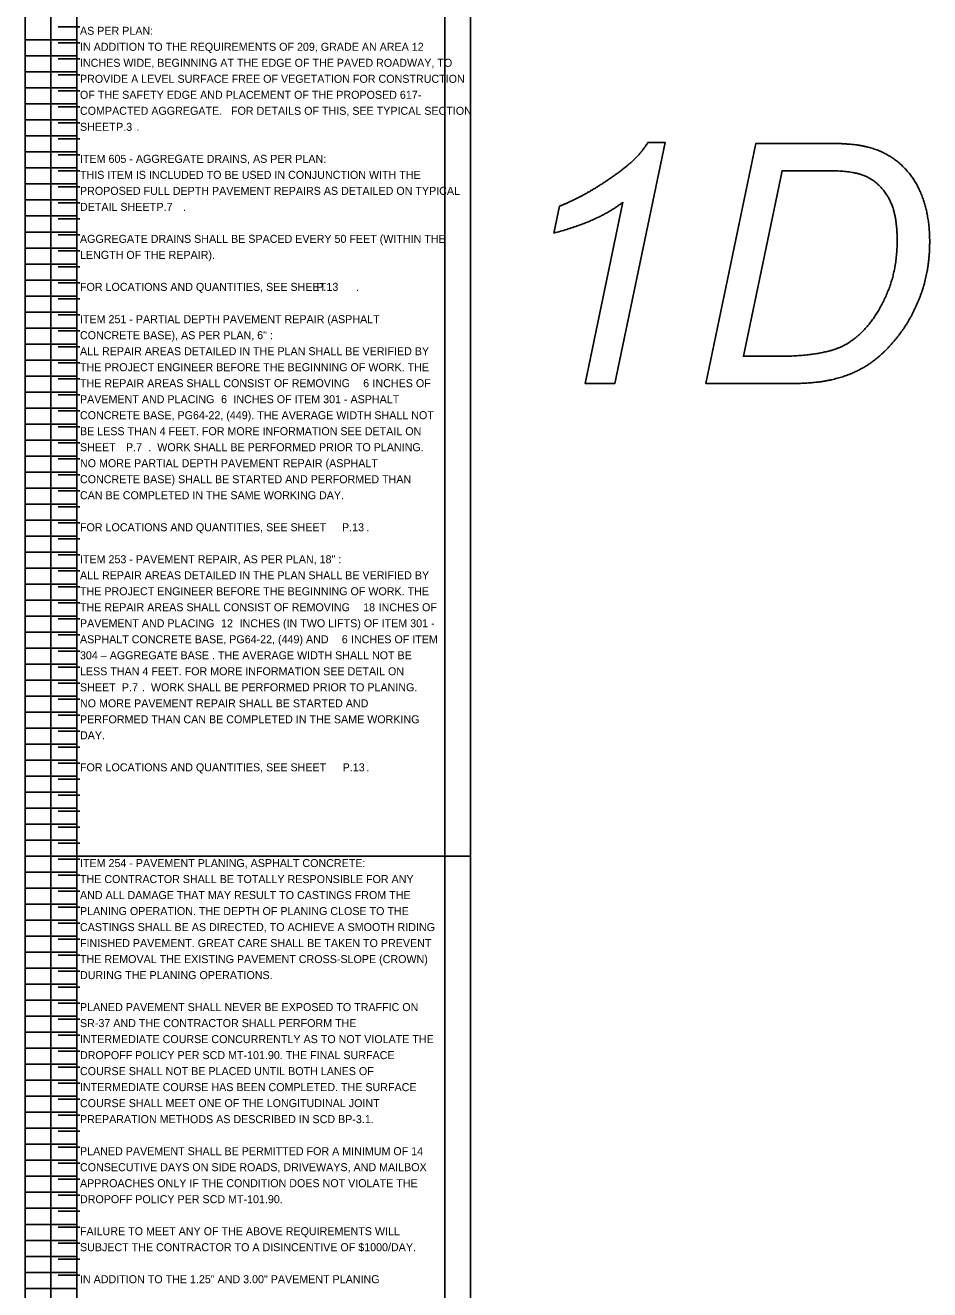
# Model space of a CAD drawing. Extents: x 12316 to 12541, y 1124 to 1850.
# Drawn here: x 12521.92 to 12537.74, y 1761.57 to 1783.69 of the extents above; entities that cross this region are included whole.
import ezdxf

# ---------------------------------------------------------------- set-up
doc = ezdxf.new("R2010")
doc.units = 0
for name, color, linetype in [('SC_Scratch1', 7, 'Continuous'), ('SH_Data', 7, 'Continuous'), ('SH_Text', 7, 'Continuous')]:
    doc.layers.add(name, color=color, linetype=linetype)

msp = doc.modelspace()

# ---------------------------------------------------------------- linework, layer by layer
at = {"layer": 'SC_Scratch1'}
for p, q in [((12521.919, 1769.151), (12521.919, 1789.311)), ((12522.819, 1769.151), (12522.819, 1789.311)), ((12522.819, 1789.311), (12522.819, 1769.151)), ((12522.876, 1783.661), (12522.492, 1783.661)), ((12521.919, 1783.431), (12522.819, 1783.431)), ((12522.876, 1783.381), (12522.492, 1783.381)), ((12521.919, 1783.151), (12522.819, 1783.151)), ((12522.876, 1783.101), (12522.492, 1783.101)), ((12521.919, 1782.871), (12522.819, 1782.871)), ((12522.876, 1782.821), (12522.492, 1782.821)), ((12521.919, 1782.591), (12522.819, 1782.591)), ((12522.876, 1782.541), (12522.492, 1782.541)), ((12521.919, 1782.311), (12522.819, 1782.311)), ((12522.876, 1782.261), (12522.492, 1782.261)), ((12521.919, 1782.031), (12522.819, 1782.031)), ((12522.876, 1781.981), (12522.492, 1781.981)), ((12521.919, 1781.751), (12522.819, 1781.751)), ((12522.876, 1781.701), (12522.492, 1781.701)), ((12521.919, 1781.471), (12522.819, 1781.471)), ((12522.876, 1781.421), (12522.492, 1781.421)), ((12521.919, 1781.191), (12522.819, 1781.191)), ((12522.876, 1781.141), (12522.492, 1781.141)), ((12521.919, 1780.911), (12522.819, 1780.911)), ((12522.876, 1780.861), (12522.492, 1780.861)), ((12521.919, 1780.631), (12522.819, 1780.631)), ((12522.876, 1780.581), (12522.492, 1780.581)), ((12531.166, 1780.052), (12531.263, 1780.523)), ((12521.919, 1780.351), (12522.819, 1780.351)), ((12522.876, 1780.301), (12522.492, 1780.301)), ((12521.919, 1780.071), (12522.819, 1780.071)), ((12522.876, 1780.021), (12522.492, 1780.021)), ((12521.919, 1779.791), (12522.819, 1779.791)), ((12522.876, 1779.741), (12522.492, 1779.741)), ((12521.919, 1779.511), (12522.819, 1779.511)), ((12522.876, 1779.461), (12522.492, 1779.461)), ((12521.919, 1779.231), (12522.819, 1779.231)), ((12522.876, 1779.181), (12522.492, 1779.181)), ((12521.919, 1778.951), (12522.819, 1778.951)), ((12522.876, 1778.901), (12522.492, 1778.901)), ((12521.919, 1778.671), (12522.819, 1778.671)), ((12522.876, 1778.621), (12522.492, 1778.621)), ((12521.919, 1778.391), (12522.819, 1778.391)), ((12522.876, 1778.341), (12522.492, 1778.341)), ((12521.919, 1778.111), (12522.819, 1778.111)), ((12522.876, 1778.061), (12522.492, 1778.061)), ((12521.919, 1777.831), (12522.819, 1777.831)), ((12522.876, 1777.781), (12522.492, 1777.781)), ((12521.919, 1777.551), (12522.819, 1777.551)), ((12522.876, 1777.501), (12522.492, 1777.501)), ((12521.919, 1777.271), (12522.819, 1777.271)), ((12522.876, 1777.221), (12522.492, 1777.221)), ((12521.919, 1776.991), (12522.819, 1776.991)), ((12522.876, 1776.941), (12522.492, 1776.941)), ((12521.919, 1776.711), (12522.819, 1776.711)), ((12522.876, 1776.661), (12522.492, 1776.661)), ((12521.919, 1776.431), (12522.819, 1776.431)), ((12522.876, 1776.381), (12522.492, 1776.381)), ((12521.919, 1776.151), (12522.819, 1776.151)), ((12522.876, 1776.101), (12522.492, 1776.101)), ((12521.919, 1775.871), (12522.819, 1775.871)), ((12522.876, 1775.821), (12522.492, 1775.821)), ((12521.919, 1775.591), (12522.819, 1775.591)), ((12522.876, 1775.541), (12522.492, 1775.541)), ((12521.919, 1775.311), (12522.819, 1775.311)), ((12522.876, 1775.261), (12522.492, 1775.261)), ((12521.919, 1775.031), (12522.819, 1775.031)), ((12522.876, 1774.981), (12522.492, 1774.981)), ((12521.919, 1774.751), (12522.819, 1774.751)), ((12522.876, 1774.701), (12522.492, 1774.701)), ((12521.919, 1774.471), (12522.819, 1774.471)), ((12522.876, 1774.421), (12522.492, 1774.421)), ((12521.919, 1774.191), (12522.819, 1774.191)), ((12522.876, 1774.141), (12522.492, 1774.141)), ((12521.919, 1773.911), (12522.819, 1773.911)), ((12522.876, 1773.861), (12522.492, 1773.861)), ((12521.919, 1773.631), (12522.819, 1773.631)), ((12522.876, 1773.581), (12522.492, 1773.581)), ((12521.919, 1773.351), (12522.819, 1773.351)), ((12522.876, 1773.301), (12522.492, 1773.301)), ((12521.919, 1773.071), (12522.819, 1773.071)), ((12522.876, 1773.021), (12522.492, 1773.021)), ((12521.919, 1772.791), (12522.819, 1772.791)), ((12522.876, 1772.741), (12522.492, 1772.741)), ((12521.919, 1772.511), (12522.819, 1772.511)), ((12522.876, 1772.461), (12522.492, 1772.461)), ((12521.919, 1772.231), (12522.819, 1772.231)), ((12522.876, 1772.181), (12522.492, 1772.181)), ((12521.919, 1771.951), (12522.819, 1771.951)), ((12522.876, 1771.901), (12522.492, 1771.901)), ((12521.919, 1771.671), (12522.819, 1771.671)), ((12522.876, 1771.621), (12522.492, 1771.621)), ((12521.919, 1771.391), (12522.819, 1771.391)), ((12522.876, 1771.341), (12522.492, 1771.341)), ((12521.919, 1771.111), (12522.819, 1771.111)), ((12522.876, 1771.061), (12522.492, 1771.061)), ((12521.919, 1770.831), (12522.819, 1770.831)), ((12522.876, 1770.781), (12522.492, 1770.781)), ((12521.919, 1770.551), (12522.819, 1770.551)), ((12522.876, 1770.501), (12522.492, 1770.501)), ((12521.919, 1770.271), (12522.819, 1770.271)), ((12522.876, 1770.221), (12522.492, 1770.221)), ((12521.919, 1769.991), (12522.819, 1769.991)), ((12522.876, 1769.941), (12522.492, 1769.941)), ((12521.919, 1769.711), (12522.819, 1769.711)), ((12522.876, 1769.661), (12522.492, 1769.661)), ((12521.919, 1769.431), (12522.819, 1769.431)), ((12522.876, 1769.381), (12522.492, 1769.381)), ((12522.819, 1769.381), (12522.819, 1728.831)), ((12521.919, 1769.151), (12522.819, 1769.151)), ((12521.919, 1748.991), (12521.919, 1769.151)), ((12521.919, 1769.151), (12522.819, 1769.151)), ((12522.876, 1769.101), (12522.492, 1769.101)), ((12522.819, 1748.991), (12522.819, 1769.151)), ((12521.919, 1768.871), (12522.819, 1768.871)), ((12522.876, 1768.821), (12522.492, 1768.821)), ((12521.919, 1768.591), (12522.819, 1768.591)), ((12522.876, 1768.541), (12522.492, 1768.541)), ((12521.919, 1768.311), (12522.819, 1768.311)), ((12522.876, 1768.261), (12522.492, 1768.261)), ((12521.919, 1768.031), (12522.819, 1768.031)), ((12522.876, 1767.981), (12522.492, 1767.981)), ((12521.919, 1767.751), (12522.819, 1767.751)), ((12522.876, 1767.701), (12522.492, 1767.701)), ((12521.919, 1767.471), (12522.819, 1767.471)), ((12522.876, 1767.421), (12522.492, 1767.421)), ((12521.919, 1767.191), (12522.819, 1767.191)), ((12522.876, 1767.141), (12522.492, 1767.141)), ((12521.919, 1766.911), (12522.819, 1766.911)), ((12522.876, 1766.861), (12522.492, 1766.861)), ((12521.919, 1766.631), (12522.819, 1766.631)), ((12522.876, 1766.581), (12522.492, 1766.581)), ((12521.919, 1766.351), (12522.819, 1766.351)), ((12522.876, 1766.301), (12522.492, 1766.301)), ((12521.919, 1766.071), (12522.819, 1766.071)), ((12522.876, 1766.021), (12522.492, 1766.021)), ((12521.919, 1765.791), (12522.819, 1765.791)), ((12522.876, 1765.741), (12522.492, 1765.741)), ((12521.919, 1765.511), (12522.819, 1765.511)), ((12522.876, 1765.461), (12522.492, 1765.461)), ((12521.919, 1765.231), (12522.819, 1765.231)), ((12522.876, 1765.181), (12522.492, 1765.181)), ((12521.919, 1764.951), (12522.819, 1764.951)), ((12522.876, 1764.901), (12522.492, 1764.901)), ((12521.919, 1764.671), (12522.819, 1764.671)), ((12522.876, 1764.621), (12522.492, 1764.621)), ((12521.919, 1764.391), (12522.819, 1764.391)), ((12522.876, 1764.341), (12522.492, 1764.341)), ((12521.919, 1764.111), (12522.819, 1764.111)), ((12522.876, 1764.061), (12522.492, 1764.061)), ((12521.919, 1763.831), (12522.819, 1763.831)), ((12522.876, 1763.781), (12522.492, 1763.781)), ((12521.919, 1763.551), (12522.819, 1763.551)), ((12522.876, 1763.501), (12522.492, 1763.501)), ((12521.919, 1763.271), (12522.819, 1763.271)), ((12522.876, 1763.221), (12522.492, 1763.221)), ((12521.919, 1762.991), (12522.819, 1762.991)), ((12522.876, 1762.941), (12522.492, 1762.941)), ((12521.919, 1762.711), (12522.819, 1762.711)), ((12522.876, 1762.661), (12522.492, 1762.661)), ((12521.919, 1762.431), (12522.819, 1762.431)), ((12522.876, 1762.381), (12522.492, 1762.381)), ((12521.919, 1762.151), (12522.819, 1762.151)), ((12522.876, 1762.101), (12522.492, 1762.101)), ((12521.919, 1761.871), (12522.819, 1761.871)), ((12522.876, 1761.821), (12522.492, 1761.821)), ((12521.919, 1761.591), (12522.819, 1761.591))]:
    msp.add_line(p, q, dxfattribs=at)
for points in [[(12522.369, 1789.311), (12529.709, 1789.311), (12529.709, 1769.151), (12522.369, 1769.151)], [(12522.819, 1789.311), (12529.259, 1789.311), (12529.259, 1769.151), (12522.819, 1769.151)], [(12522.369, 1769.151), (12529.709, 1769.151), (12529.709, 1748.991), (12522.369, 1748.991)], [(12522.819, 1769.151), (12529.259, 1769.151), (12529.259, 1748.991), (12522.819, 1748.991)]]:
    msp.add_lwpolyline(points, close=True, dxfattribs=at)
for points in [[(12532.811, 1781.637), (12533.111, 1781.637), (12532.234, 1777.421), (12531.712, 1777.421), (12532.375, 1780.594)], [(12535.966, 1781.621), (12534.699, 1781.621), (12533.822, 1777.421), (12535.335, 1777.421)], [(12535.147, 1777.898), (12534.481, 1777.898), (12535.159, 1781.144), (12535.903, 1781.144)]]:
    msp.add_lwpolyline(points, dxfattribs=at)
for points in [[(12532.593, 1781.36), (12532.707, 1781.474), (12532.811, 1781.637)], [(12536.663, 1781.555), (12536.422, 1781.621), (12535.966, 1781.621)], [(12537.25, 1781.238), (12537.007, 1781.466), (12536.663, 1781.555)], [(12532.027, 1780.926), (12532.404, 1781.174), (12532.593, 1781.36)], [(12535.903, 1781.144), (12536.334, 1781.144), (12536.538, 1781.078)], [(12537.617, 1780.67), (12537.494, 1781.011), (12537.25, 1781.238)], [(12531.263, 1780.523), (12531.65, 1780.677), (12532.027, 1780.926)], [(12536.538, 1781.078), (12536.814, 1780.989), (12536.992, 1780.716)], [(12536.992, 1780.716), (12537.171, 1780.442), (12537.171, 1779.932)], [(12537.74, 1779.905), (12537.74, 1780.329), (12537.617, 1780.67)], [(12532.375, 1780.594), (12531.945, 1780.256), (12531.166, 1780.052)], [(12537.171, 1779.932), (12537.171, 1779.474), (12537.04, 1779.114)], [(12537.587, 1778.981), (12537.74, 1779.398), (12537.74, 1779.905)], [(12537.04, 1779.114), (12536.909, 1778.755), (12536.691, 1778.474)], [(12537.186, 1778.247), (12537.434, 1778.564), (12537.587, 1778.981)], [(12536.691, 1778.474), (12536.525, 1778.262), (12536.321, 1778.133)], [(12536.667, 1777.752), (12536.938, 1777.931), (12537.186, 1778.247)], [(12536.321, 1778.133), (12536.166, 1778.033), (12535.948, 1777.981)], [(12535.948, 1777.981), (12535.597, 1777.898), (12535.147, 1777.898)], [(12536.026, 1777.487), (12536.396, 1777.573), (12536.667, 1777.752)], [(12535.335, 1777.421), (12535.745, 1777.421), (12536.026, 1777.487)]]:
    msp.add_open_spline(points, degree=2, dxfattribs=at)

# ---------------------------------------------------------------- texts
at = {"layer": 'SH_Data'}
for s, p in [('AS PER PLAN:', (12522.876, 1783.521)), ('IN ADDITION TO THE REQUIREMENTS OF 209, GRADE AN AREA 12  ', (12522.876, 1783.241)), ('INCHES WIDE, BEGINNING AT THE EDGE OF THE PAVED ROADWAY, TO ', (12522.876, 1782.961)), ('PROVIDE A LEVEL SURFACE FREE OF VEGETATION FOR CONSTRUCTION ', (12522.876, 1782.681)), ('OF THE SAFETY EDGE AND PLACEMENT OF THE PROPOSED 617-', (12522.876, 1782.401)), ('COMPACTED AGGREGATE.   FOR DETAILS OF THIS, SEE TYPICAL SECTION ', (12522.876, 1782.121)), ('SHEET       .', (12522.876, 1781.841)), ('ITEM 605 - AGGREGATE DRAINS, AS PER PLAN:', (12522.876, 1781.281)), ('THIS ITEM IS INCLUDED TO BE USED IN CONJUNCTION WITH THE ', (12522.876, 1781.001)), ('PROPOSED FULL DEPTH PAVEMENT REPAIRS AS DETAILED ON TYPICAL ', (12522.876, 1780.721)), ('DETAIL SHEET         .', (12522.876, 1780.441)), ('AGGREGATE DRAINS SHALL BE SPACED EVERY 50 FEET (WITHIN THE ', (12522.876, 1779.881)), ('LENGTH OF THE REPAIR).', (12522.876, 1779.601)), ('FOR LOCATIONS AND QUANTITIES, SEE SHEET          .', (12522.876, 1779.041))]:
    msp.add_text(s, height=0.14, dxfattribs=at).set_placement(p)
at = {"layer": 'SH_Text'}
for s, p in [('P.3', (12523.508, 1781.841)), ('P.7', (12524.215, 1780.441)), ('P.13', (12527.01, 1779.041)), ('ITEM 251 - PARTIAL DEPTH PAVEMENT REPAIR (ASPHALT ', (12522.876, 1778.476)), ('CONCRETE BASE), AS PER PLAN, 6" :', (12522.876, 1778.196)), ('ALL REPAIR AREAS DETAILED IN THE PLAN SHALL BE VERIFIED BY ', (12522.876, 1777.916)), ('THE PROJECT ENGINEER BEFORE THE BEGINNING OF WORK. THE ', (12522.876, 1777.636)), ('THE REPAIR AREAS SHALL CONSIST OF REMOVING ', (12522.876, 1777.356)), ('6 ', (12527.83, 1777.356)), ('INCHES OF ', (12527.993, 1777.356)), ('PAVEMENT AND PLACING ', (12522.876, 1777.076)), ('6 ', (12525.344, 1777.076)), (' INCHES OF ITEM 301 - ASPHALT ', (12525.507, 1777.076)), ('CONCRETE BASE, PG64-22, (449). THE AVERAGE WIDTH SHALL NOT ', (12522.876, 1776.796)), ('BE LESS THAN 4 FEET. FOR MORE INFORMATION SEE DETAIL ON ', (12522.876, 1776.516)), ('SHEET', (12522.876, 1776.236)), ('P.7', (12523.681, 1776.236)), ('.  WORK SHALL BE PERFORMED PRIOR TO PLANING. ', (12524.072, 1776.236)), ('NO MORE PARTIAL DEPTH PAVEMENT REPAIR (ASPHALT ', (12522.876, 1775.956)), ('CONCRETE BASE) SHALL BE STARTED AND PERFORMED THAN ', (12522.876, 1775.676)), ('CAN BE COMPLETED IN THE SAME WORKING DAY.', (12522.876, 1775.396)), ('FOR LOCATIONS AND QUANTITIES, SEE SHEET  ', (12522.876, 1774.836)), ('P.13', (12527.46, 1774.836)), (' .', (12527.836, 1774.836)), ('ITEM 253 - PAVEMENT REPAIR, AS PER PLAN, 18" :', (12522.876, 1774.276)), ('ALL REPAIR AREAS DETAILED IN THE PLAN SHALL BE VERIFIED BY ', (12522.876, 1773.996)), ('THE PROJECT ENGINEER BEFORE THE BEGINNING OF WORK. THE ', (12522.876, 1773.716)), ('THE REPAIR AREAS SHALL CONSIST OF REMOVING ', (12522.876, 1773.436)), ('18 ', (12527.83, 1773.436)), ('INCHES OF ', (12528.101, 1773.436)), ('PAVEMENT AND PLACING ', (12522.876, 1773.156)), ('12 ', (12525.344, 1773.156)), (' INCHES (IN TWO LIFTS) OF ITEM 301 - ', (12525.616, 1773.156)), ('ASPHALT CONCRETE BASE, PG64-22, (449) AND ', (12522.876, 1772.876)), ('6', (12527.456, 1772.876)), (' INCHES OF ITEM ', (12527.565, 1772.876)), ('304 – AGGREGATE BASE . THE AVERAGE WIDTH SHALL NOT BE ', (12522.876, 1772.596)), ('LESS THAN 4 FEET. FOR MORE INFORMATION SEE DETAIL ON ', (12522.876, 1772.316)), ('SHEET', (12522.876, 1772.036)), ('P.7', (12523.61, 1772.036)), (' .  WORK SHALL BE PERFORMED PRIOR TO PLANING. ', (12523.909, 1772.036)), ('NO MORE PAVEMENT REPAIR SHALL BE STARTED AND ', (12522.876, 1771.756)), ('PERFORMED THAN CAN BE COMPLETED IN THE SAME WORKING ', (12522.876, 1771.476)), ('DAY.', (12522.876, 1771.196)), ('FOR LOCATIONS AND QUANTITIES, SEE SHEET  ', (12522.876, 1770.636)), ('P.13', (12527.471, 1770.636)), (' .', (12527.836, 1770.636)), ('ITEM 254 - PAVEMENT PLANING, ASPHALT CONCRETE:', (12522.876, 1768.961)), ('THE CONTRACTOR SHALL BE TOTALLY RESPONSIBLE FOR ANY ', (12522.876, 1768.681)), ('AND ALL DAMAGE THAT MAY RESULT TO CASTINGS FROM THE ', (12522.876, 1768.401)), ('PLANING OPERATION. THE DEPTH OF PLANING CLOSE TO THE ', (12522.876, 1768.121)), ('CASTINGS SHALL BE AS DIRECTED, TO ACHIEVE A SMOOTH RIDING ', (12522.876, 1767.841)), ('FINISHED PAVEMENT. GREAT CARE SHALL BE TAKEN TO PREVENT ', (12522.876, 1767.561)), ('THE REMOVAL THE EXISTING PAVEMENT CROSS-SLOPE (CROWN) ', (12522.876, 1767.281)), ('DURING THE PLANING OPERATIONS.', (12522.876, 1767.001)), ('PLANED PAVEMENT SHALL NEVER BE EXPOSED TO TRAFFIC ON ', (12522.876, 1766.441)), ('SR-37 AND THE CONTRACTOR SHALL PERFORM THE ', (12522.876, 1766.161)), ('INTERMEDIATE COURSE CONCURRENTLY AS TO NOT VIOLATE THE ', (12522.876, 1765.881)), ('DROPOFF POLICY PER SCD MT-101.90. THE FINAL SURFACE ', (12522.876, 1765.601)), ('COURSE SHALL NOT BE PLACED UNTIL BOTH LANES OF ', (12522.876, 1765.321)), ('INTERMEDIATE COURSE HAS BEEN COMPLETED. THE SURFACE ', (12522.876, 1765.041)), ('COURSE SHALL MEET ONE OF THE LONGITUDINAL JOINT ', (12522.876, 1764.761)), ('PREPARATION METHODS AS DESCRIBED IN SCD BP-3.1.', (12522.876, 1764.481)), ('PLANED PAVEMENT SHALL BE PERMITTED FOR A MINIMUM OF 14 ', (12522.876, 1763.921)), ('CONSECUTIVE DAYS ON SIDE ROADS, DRIVEWAYS, AND MAILBOX ', (12522.876, 1763.641)), ('APPROACHES ONLY IF THE CONDITION DOES NOT VIOLATE THE ', (12522.876, 1763.361)), ('DROPOFF POLICY PER SCD MT-101.90. ', (12522.876, 1763.081)), ('FAILURE TO MEET ANY OF THE ABOVE REQUIREMENTS WILL ', (12522.876, 1762.521)), ('SUBJECT THE CONTRACTOR TO A DISINCENTIVE OF $1000/DAY.', (12522.876, 1762.241)), ('IN ADDITION TO THE 1.25" AND 3.00" PAVEMENT PLANING ', (12522.876, 1761.681))]:
    msp.add_text(s, height=0.14, dxfattribs=at).set_placement(p)

doc.saveas('drawing.dxf')
